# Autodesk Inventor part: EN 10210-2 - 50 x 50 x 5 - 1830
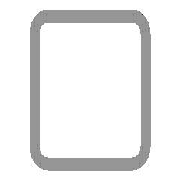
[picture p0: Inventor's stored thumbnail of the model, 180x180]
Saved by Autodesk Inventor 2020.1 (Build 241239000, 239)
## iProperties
_CCFamilyMember: 16
_CCFamilyDisplayName: DIN EN 10210-2 (USAS B17.1 quadratisch) - Rohrleitung — In Klammern angegebene Größen wurden aufgehoben
_FrameMemberDoc: Frame Member File
_Version: 15.0.0
_GetPNFromCC: 1
Created: 2019-01
Part Number: EN 10210-2 - 50 x 50 x 5 - 1830
Material: Stahl, weich
Description: Rohrleitung
Document SubType Name: Modeling
Standard: DIN
Designer: lutzd
Standard Revision: 2006-07
Standards Organization: DIN
Language: de-DE
Size Designation: 50 x 50 x 5
Categories: <MemberInstance><Categories><Category DisplayName="Profile" InternalName="089c4875-fa83-4c05-b084-43b9cc11f5ed" Mnemonic="GRDR"><CategoryParameter DisplayName="
Stock Number: 50 x 50 x 5
Mass: 12537.4 g
Surface Area: 6214.37 cm^2
Volume: 1597.12 cm^3
Density: 7.85 g/cm^3
Appearance: Halbpoliert
G_L: 1830,000 mm
G_W: 50,000 mm
G_H: 50,000 mm
DocNumber: ADSK-014145
Folder: .
Dimensions: 50x50x1830 mm
Mass: 12,537 kg
IsCustomPart: 1
Title: Profil-Bauteil
Author: lutzd
Revision Number: -
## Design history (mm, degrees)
node "Startebene"
node "Endebene"
sketch "Skizze"
  geometry: L1 (-25, -17.5)-(-25, 17.5); L2 (-17.5, 25)-(17.5, 25); L3 (25, 17.5)-(25, -17.5); L4 (17.5, -25)-(-17.5, -25); L5 (-15, 20)-(15, 20); L6 (20, 15)-(20, -15); L7 (15, -20)-(-15, -20); L8 (-20, -15)-(-20, 15); L9 (0, 37.175)-(0, -37.175) reference; L10 (-37.175, 0)-(37.175, 0) reference; A1 r 7.5 centre (-17.5, -17.5) between (-25, -17.5) and (-17.5, -25); A2 r 7.5 centre (-17.5, 17.5) between (-17.5, 25) and (-25, 17.5); A3 r 7.5 centre (17.5, 17.5) between (25, 17.5) and (17.5, 25); A4 r 7.5 centre (17.5, -17.5) between (17.5, -25) and (25, -17.5); A5 r 5 centre (-15, -15) between (-20, -15) and (-15, -20); A6 r 5 centre (-15, 15) between (-15, 20) and (-20, 15); A7 r 5 centre (15, 15) between (20, 15) and (15, 20); A8 r 5 centre (15, -15) between (15, -20) and (20, -15)
  constraints: 16 end point, 16 point on circle, 16 tangent, 8 centre point, 6 equal radius, 4 parallel, 2 perpendicular, 2 other
  dimensions: "d7" = 7.5 radius of A1 (= G_IR); "d10" = 50 distance between parallel lines of L2 L4 (= G_H); "d11" = 50 distance between parallel lines of L1 L3 (= G_W); "d12" = 5 distance between parallel lines of L3 L6 (= G_T); "d15" = 25 distance between parallel lines of L2 L10 (= 0.5 x d10); "d16" = 25 distance between parallel lines of L9 L3 (= 0.5 x d11); "d19" = 5 radius of A5 (= G_T); "d20" = 5 distance between parallel lines of L4 L7 (= G_T)
extrude "Körper" new body sketch "Skizze" stored distance "d3" = 1830 (= G_L); taper "d4" = 0 deg
node "Driven Length"
  sketch "Sketch3"
    geometry: L1 (0, 0)-(10, 0) reference
    constraints: 2 end point, 1 horizontal
  workplane "Work Plane3"
  sketch "Sketch4"
    geometry: L1 (-2, 0)-(12, 0) reference; L2 (-2, 1830)-(12, 1830) reference
    dimensions: "d18" = 1830 distance between parallel lines of L1 L2 (derived)
sketch "Skizze5"
  geometry: L1 (-35, 0)-(0, 0) reference; L2 (-17.5, 0)-(-17.5, 648); 5 further points
  constraints: 3 point on line, 2 end point, 1 coincident, 1 midpoint, 1 vertical
  dimensions: "d21" = 76 distance of point (-17.5, 572) point (-17.5, 648); "d22" = 76 distance of point (-17.5, 496) point (-17.5, 572) (= d21); "d23" = 76 distance of point (-17.5, 420) point (-17.5, 496) (= d21); "d24" = 420 distance from line of L1 point (-17.5, 420)
hole "Bohrung1" sketch "Skizze5" at (-17.5, 648), (-17.5, 572), (-17.5, 496), (-17.5, 420) diameter "d25" = 6.647; stored, may be unused: countersink angle "d29" = 90 deg, drill point angle "d31" = 118 deg; dims "d26" = 16, "d27" = 4, "d28" = 2, "d30" = 8
body "Solid1"
other parameters: "G_W" = 50 [user parameter; used in 1 equation term], "G_H" = 50 [user parameter; used in 1 equation term], "G_T" = 5 [user parameter; used in 3 equation terms], "G_IR" = 7.5 [user parameter; used in 1 equation term], "G_L" = 1830 (= d18) [user parameter; used in 1 equation term], "G_OFFSET_START" = 0 [user parameter; used in 1 equation term], "G_OFFSET_END" = 0 [user parameter; used in 1 equation term], "d13" = 0 (computed from G_OFFSET_START), "d17" = 90 deg
